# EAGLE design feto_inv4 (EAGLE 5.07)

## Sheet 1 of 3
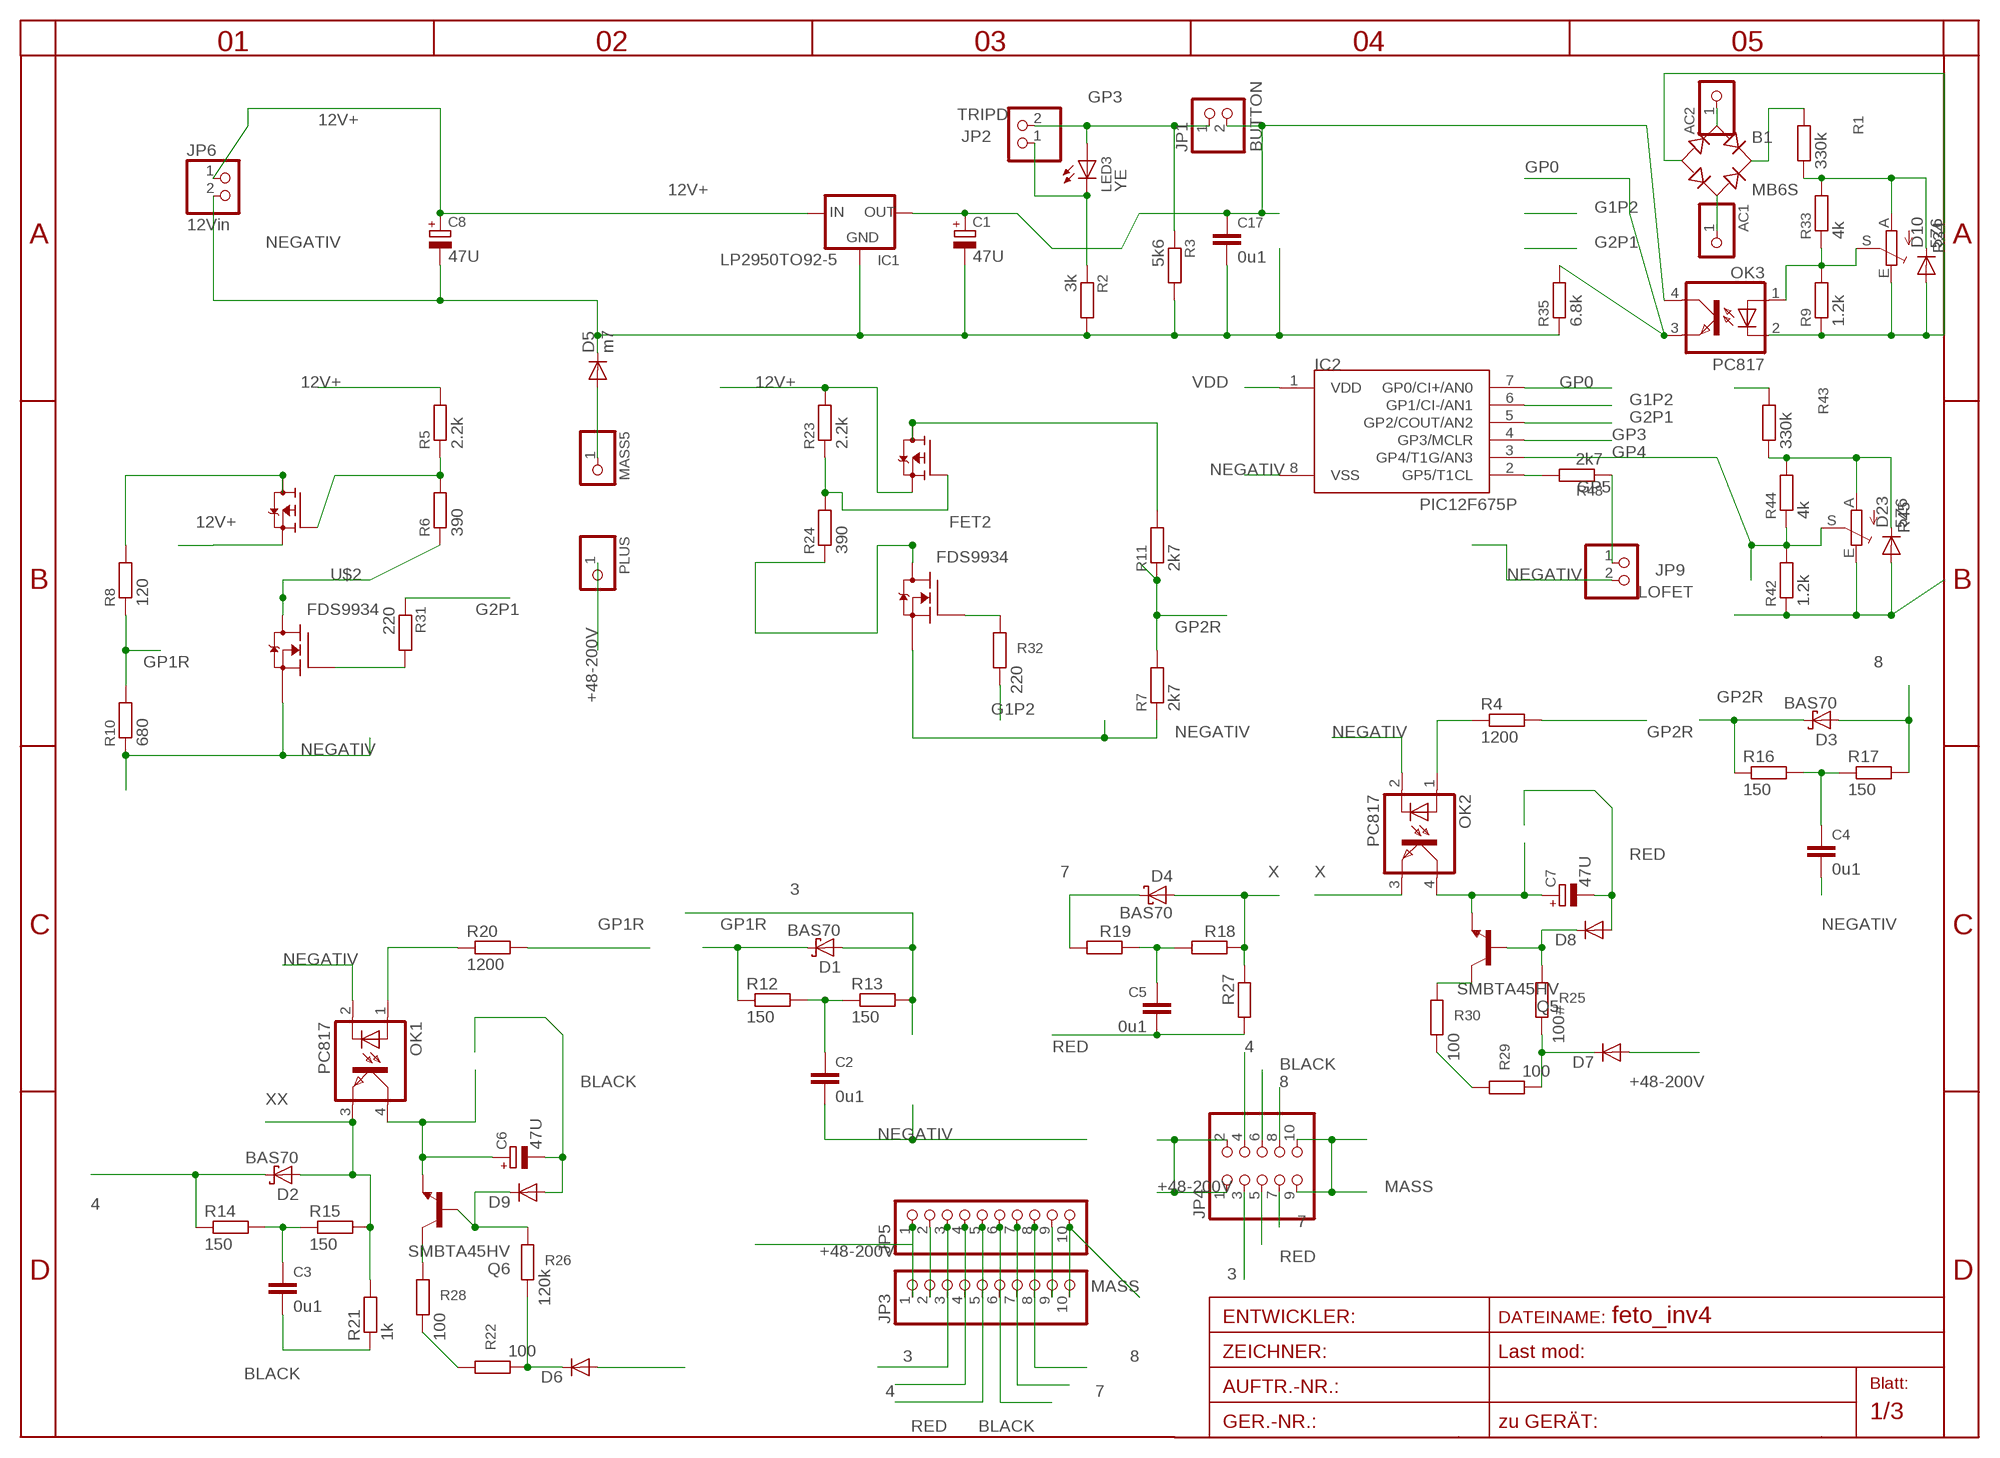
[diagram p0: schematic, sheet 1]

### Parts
AC1  PINHD-1X11MM6  [1X1MM8]
AC2  PINHD-1X11MM6  [1X1MM8]
B1  MB6S  [SOIC-4]
C1  47U  CPOL-EUE2.5-5  [E2,5-5]
C2  0u1  C-EUC1206  [C1206]
C3  0u1  C-EUC0805  [C0805]
C4  0u1  C-EUC1206  [C1206]
C5  0u1  C-EUC0805  [C0805]
C6  47U  CPOL-EUE2.5-6  [E2,5-6]
C7  47U  CPOL-EUE2.5-6  [E2,5-6]
C8  47U  CPOL-EUE2.5-7  [E2,5-7]
C17  0u1  C-EUC1206  [C1206]
D1  BAS70  [SOT23]
D2  BAS70  [SOT23]
D3  BAS70  [SOT23]
D4  BAS70  [SOT23]
D5  m7  DIODE-SMA-DO214  [SMA-DO214AC]
D6  DIODE-SMA-DO214  [SMA-DO214AC]
D7  DIODE-SMA-DO214  [SMA-DO214AC]
D8  DIODE-MINIMELF  [MINIMELF]
D9  DIODE-MINIMELF  [MINIMELF]
D10  5Z6  DIODE-MINIMELF  [MINIMELF]
D23  5Z6  DIODE-MINIMELF  [MINIMELF]
FET2  FDS9934  [SO-8]
IC1  LP2950TO92-5  [T092-5]
IC2  PIC12F675P  [DIL8]
JP1  BUTTON  PINHD-1X2STR  [1X02]
JP2  TRIPD  PINHD-1X2STR  [1X02]
JP3  PINHD-1X10  [1X10WIDE]
JP4  PINHD-2X5  [2X05]
JP5  PINHD-1X10  [1X10WIDE]
JP6  12Vin  PINHD-1X2STR  [1X02]
JP9  LOFET  PINHD-1X2STR  [1X02]
LED3  YE  LEDCHIPLED_1206  [CHIPLED_1206]
MASS5  PINHD-1X11MM6  [1X1MM8]
OK1  PC817  [DIL04]
OK2  PC817  [DIL04]
OK3  PC817  [DIL04]
PLUS  PINHD-1X11MM6  [1X1MM8]
Q5  SMBTA45HV  [SOT23HV]
Q6  SMBTA45HV  [SOT23HV]
R1  330k  R-EU_0204/5  [0204/5]
R2  3k  R-EU_R0805  [R0805]
R3  5k6  R-EU_R0805  [R0805]
R4  1200  R-EU_0204/7  [0204/7]
R5  2.2k  R-EU_R0805  [R0805]
R6  390  R-EU_R0805  [R0805]
R7  2k7  R-EU_R0805  [R0805]
R8  120  R-EU_R0805  [R0805]
R9  1.2k  R-EU_R0805  [R0805]
R10  680  R-EU_R0805  [R0805]
R11  2k7  R-EU_R0805  [R0805]
R12  150  R-EU_R0805  [R0805]
R13  150  R-EU_R0805  [R0805]
R14  150  R-EU_R0805  [R0805]
R15  150  R-EU_R0805  [R0805]
R16  150  R-EU_R0805  [R0805]
R17  150  R-EU_R0805  [R0805]
R18  R-EU_R0805  [R0805]
R19  R-EU_R0805  [R0805]
R20  1200  R-EU_0617/17  [0617/17]
R21  1k  R-EU_R0805  [R0805]
R22  100  R-EU_R1206  [R1206]
R23  2.2k  R-EU_R0805  [R0805]
R24  390  R-EU_R0805  [R0805]
R25  100#  R-EU_R1206  [R1206]
R26  120k  R-EU_R1206  [R1206]
R27  R-EU_R0805  [R0805]
R28  100  R-EU_R1206  [R1206]
R29  100  R-EU_R1206  [R1206]
R30  100  R-EU_R1206  [R1206]
R31  220  R-EU_R1206  [R1206]
R32  220  R-EU_R1206  [R1206]
R33  4k  R-EU_R0805  [R0805]
R34  TRIM_EU-S64W  [S64W]
R35  6.8k  R-EU_R0805  [R0805]
R42  1.2k  R-EU_R0805  [R0805]
R43  330k  R-EU_0207/50  [0207/50]
R44  4k  R-EU_R0805  [R0805]
R45  TRIM_EU-S64W  [S64W]
R48  2k7  R-EU_R0805  [R0805]
U$2  FDS9934  [SO-8]

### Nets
3: D1.1(A) JP3.3 JP4.3 JP5.3 R13.2 ; also sheet 3
4: D2.3(C) JP3.4 JP4.4 JP5.4 R14.1 ; also sheet 3
7: D4.3(C) JP3.7 JP4.7 JP5.7 R19.2 ; also sheet 3
8: D3.1(A) JP3.8 JP4.8 JP5.8 R17.2 ; also sheet 3
12V+: C8.+ FET2.3(Q2S) IC1.3(IN) JP6.1 R5.2 R23.2 U$2.3(Q2S)
+48-200V: D6.A D7.A JP3.1 JP4.1 JP4.2 JP5.1 PLUS.1 R43.2
BLACK: C3.2 C6.- D9.A JP3.6 JP4.6 JP5.6 R21.1 ; also sheet 3
G1P2: IC2.6(GP1/CI-/AN1) R32.1
G2P1: IC2.5(GP2/COUT/AN2) R31.1
GP0: IC2.7(GP0/CI+/AN0) OK3.3(EMIT) R35.2
GP1R: D1.3(C) R8.1 R10.2 R12.1 R20.2
GP2R: D3.3(C) R4.2 R7.2 R11.1 R16.1
GP3: IC2.4(GP3/MCLR) JP1.1 JP2.2 LED3.A R3.1 ; also sheet 3
GP4: IC2.3(GP4/T1G/AN3) R42.2 R44.1 R45.S
GP5: JP9.1 R48.1
MASS: D5.A JP3.10 JP4.9 JP4.10 JP5.10 MASS5.1 ; also sheet 3
N$2: FET2.2(Q1G) R32.2
N$3: C3.1 R14.2 R15.1
N$4: R5.1 R6.2 U$2.4(Q2G)
N$5: FET2.5(Q2D2) FET2.6(Q2D) R11.2
N$6: R31.2 U$2.2(Q1G)
N$7: C6.+ OK1.4(COL) Q6.2(E)
N$8: C5.1 R18.2 R19.1
N$9: FET2.7(Q1D2) FET2.8(Q1D1) R24.1
N$11: R6.1 U$2.7(Q1D2) U$2.8(Q1D1)
N$12: C2.1 R12.2 R13.1
N$13: OK2.1(A) R4.1
N$14: C7.+ OK2.4(COL) Q5.2(E)
N$15: JP2.1 LED3.C R2.1
N$16: C4.1 R16.2 R17.1
N$17: OK1.1(A) R20.1
N$20: D7.K(C) R25.1 R29.1
N$21: R8.2 U$2.5(Q2D2) U$2.6(Q2D)
N$22: FET2.4(Q2G) R23.1 R24.2
N$23: D6.K(C) R22.1 R26.1
N$24: Q6.3(C) R28.2
N$25: JP3.2 JP5.2
N$26: R22.2 R28.1
N$27: D9.C Q6.1(B) R26.2
N$28: R29.2 R30.1
N$31: D8.C Q5.1(B) R25.2
N$33: Q5.3(C) R30.2
N$34: JP3.9 JP5.9
N$35: OK3.1(A) R9.2 R33.1 R34.S
N$36: D10.C R1.1 R33.2 R34.A
N$37: B1.- D10.A OK3.2(C) R9.1 R34.E
N$38: AC1.1 B1.~2(AC2)
N$39: AC2.1 B1.~1(AC1)
N$40: B1.+ R1.2
N$41: D23.C R43.1 R44.2 R45.A
N$46: IC2.2(GP5/T1CL) R48.2
NEGATIV: C1.- C2.2 C4.2 C8.- C17.2 D5.K(C) D23.A FET2.1(Q1S) IC1.2(GND) IC2.8(VSS) JP6.2 JP9.2 OK1.2(C) OK2.2(C) R2.2 R3.2 R7.1 R10.1 R35.1 R42.1 R45.E U$2.1(Q1S)
RED: C5.2 C7.- D8.A JP3.5 JP4.5 JP5.5 R27.2 ; also sheet 3
VDD: C1.+ C17.1 IC1.1(OUT) IC2.1(VDD) JP1.2 OK3.4(COL) ; also sheet 3
X: D4.1(A) OK2.3(EMIT) R18.1 R27.1
XX: D2.1(A) OK1.3(EMIT) R15.2 R21.2

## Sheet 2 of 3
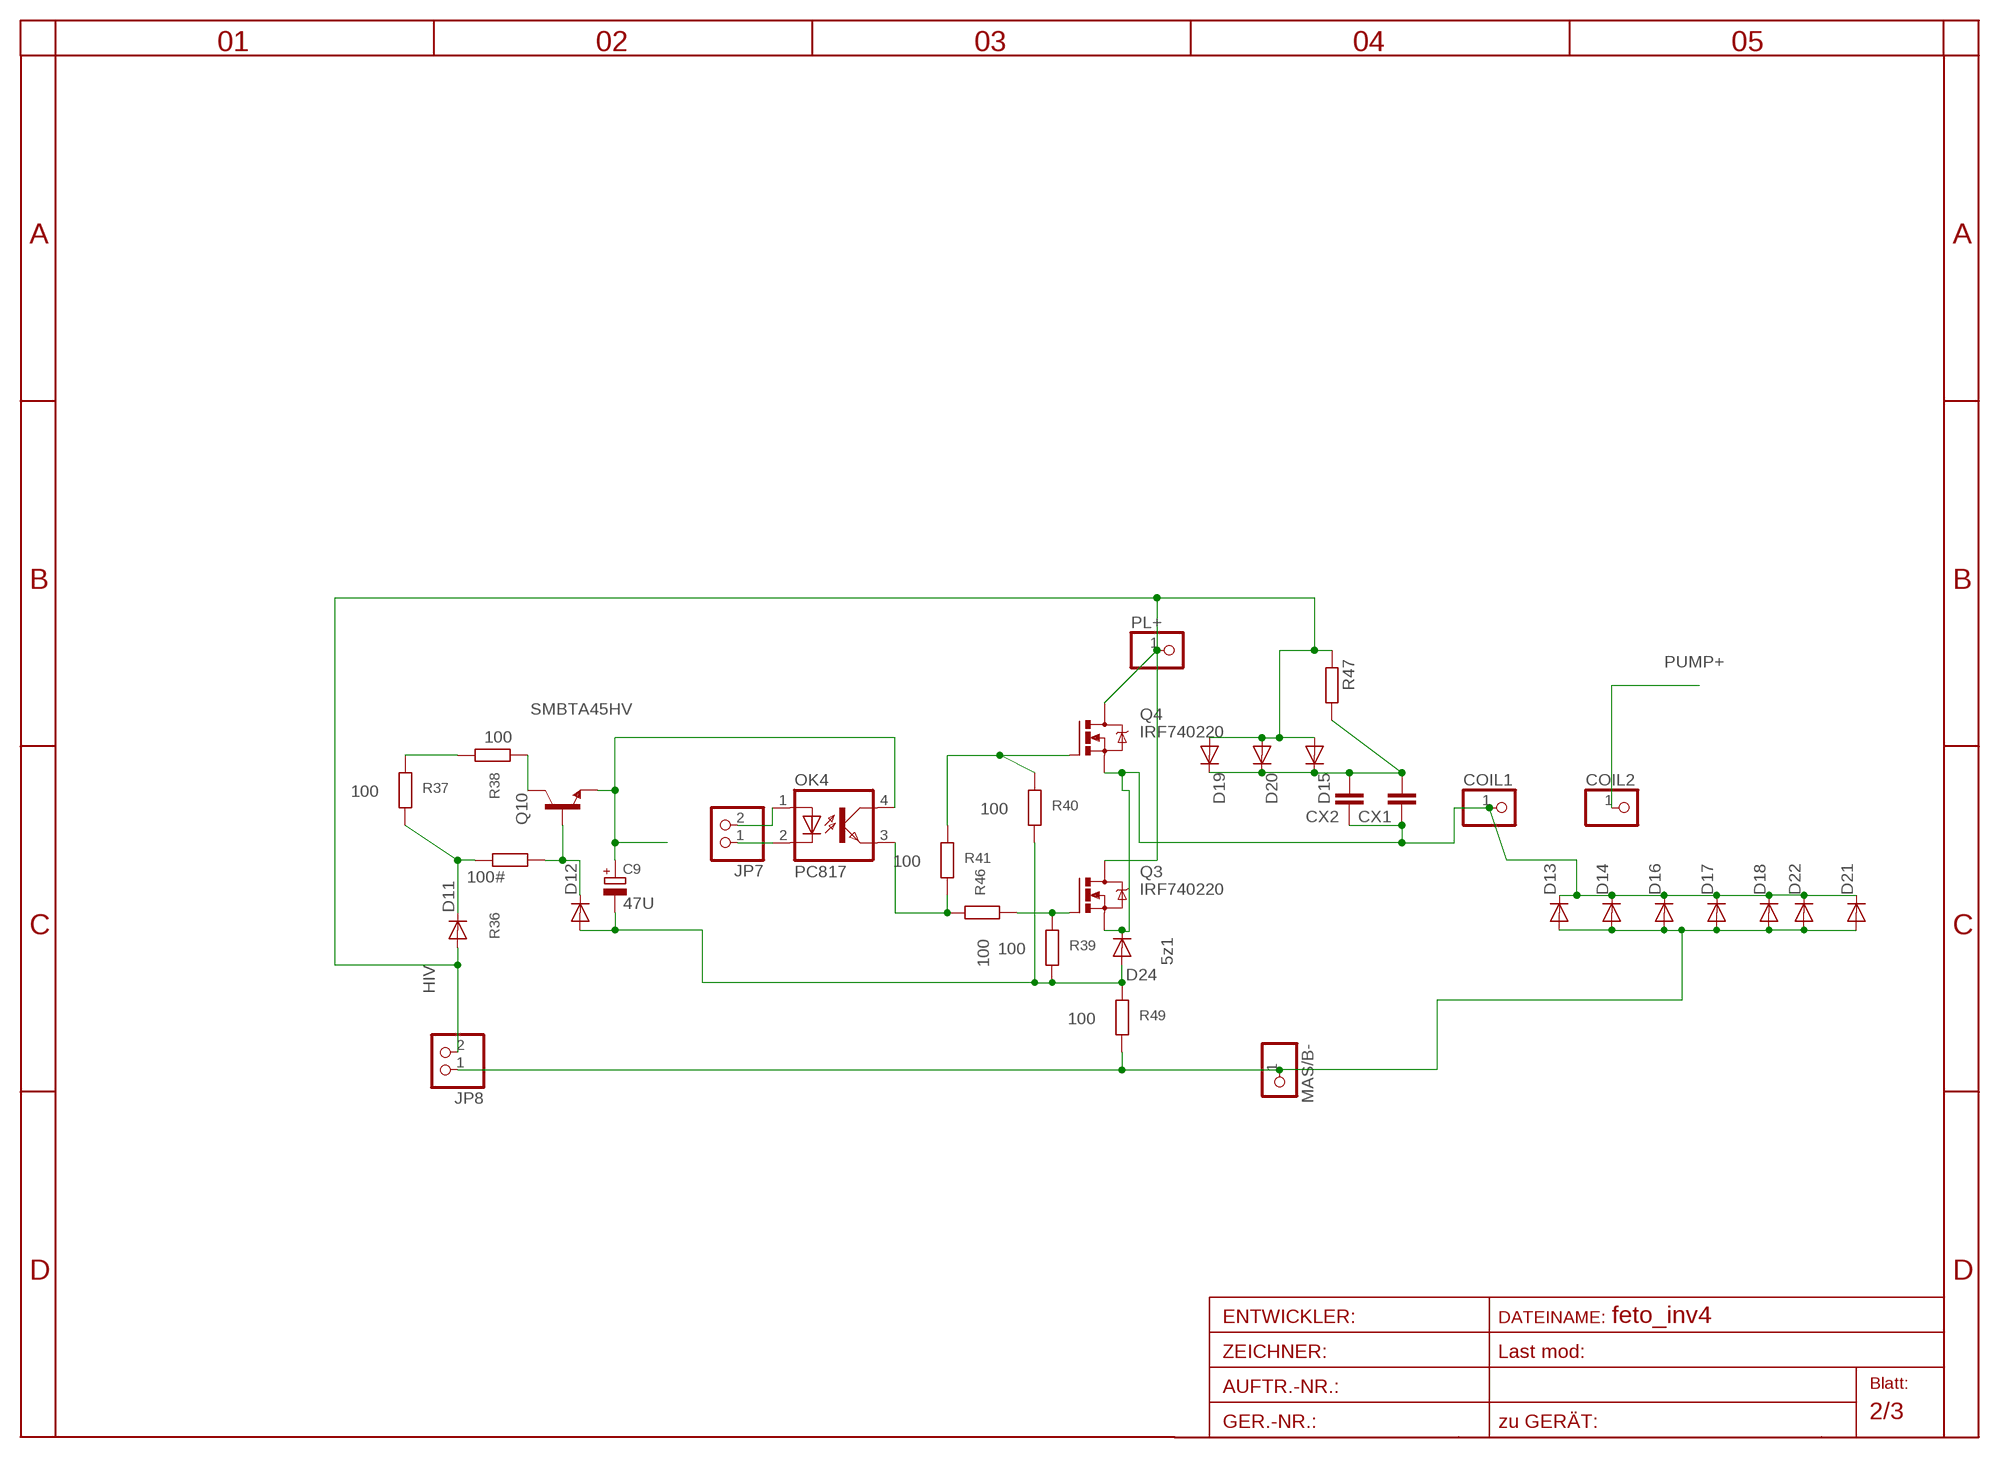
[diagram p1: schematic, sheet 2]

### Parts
C9  47U  CPOL-EUE2.5-6  [E2,5-6]
COIL1  PINHD-1X14.5MM  [1X4MM5]
COIL2  PINHD-1X14.5MM  [1X4MM5]
CX1  CXXC15B6  [XC15B6]
CX2  CXXC15B6  [XC15B6]
D11  DIODE-SMA-DO214  [SMA-DO214AC]
D12  DIODE-MINIMELF  [MINIMELF]
D13  DIODE-SMC  [SMC]
D14  DIODE-SMC  [SMC]
D15  DIODE-SMC  [SMC]
D16  DIODE-SMC  [SMC]
D17  DIODE-SMC  [SMC]
D18  DIODE-SMC  [SMC]
D19  DIODE-SMC  [SMC]
D20  DIODE-SMC  [SMC]
D21  DIODE-SMC  [SMC]
D22  DIODE-SMC  [SMC]
D24  5z1  DIODE-MINIMELF  [MINIMELF]
JP7  PINHD-1X2STR  [1X02]
JP8  PINHD-1X2STR  [1X02]
MAS/B-  PINHD-1X14.5MM  [1X4MM5]
OK4  PC817  [DIL04]
PL+  PINHD-1X14.5MM  [1X4MM5]
Q3  IRF740220  [TO220BV]
Q4  IRF740220  [TO220BV]
Q10  SMBTA45HV  [SOT23HV]
R36  100#  R-EU_R1206  [R1206]
R37  100  R-EU_R1206  [R1206]
R38  100  R-EU_R1206  [R1206]
R39  100  R-EU_0207/30  [0207/30]
R40  100  R-EU_0207/15  [0207/15]
R41  100  R-EU_0207/12  [0207/12]
R46  100  R-EU_0207/25  [0207/25]
R47  R-EU_CERAM35  [CERAM35]
R49  100  R-EU_R1206  [R1206]

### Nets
BATT-: C9.- D12.A D24.A R39.1 R40.1 R49.2
COIL1: COIL1.1 CX1.1 CX2.1 D13.C D14.C D16.C D17.C D18.C D21.C D22.C D24.C Q3.S Q4.S
HIV: D11.A D15.A D19.A D20.A JP8.2 PL+.1 Q3.D Q4.D R47.1
MINUS: D13.A D14.A D16.A D17.A D18.A D21.A D22.A JP8.1 MAS/B-.1 R49.1 ; also sheet 3
N$1: Q4.G R40.2 R41.2
N$42: JP7.1 OK4.2(C)
N$43: OK4.3(EMIT) R41.1 R46.2
N$44: JP7.2 OK4.1(A)
N$45: Q3.G R39.2 R46.1
N$48: C9.+ OK4.4(COL) Q10.2(E)
N$49: D11.K(C) R36.1 R37.1
N$50: R37.2 R38.1
N$51: D12.C Q10.1(B) R36.2
PUMP+: COIL2.1 ; also sheet 3
Q1: Q10.3(C) R38.2
SNUB: CX1.2 CX2.2 D15.C D19.C D20.C R47.2

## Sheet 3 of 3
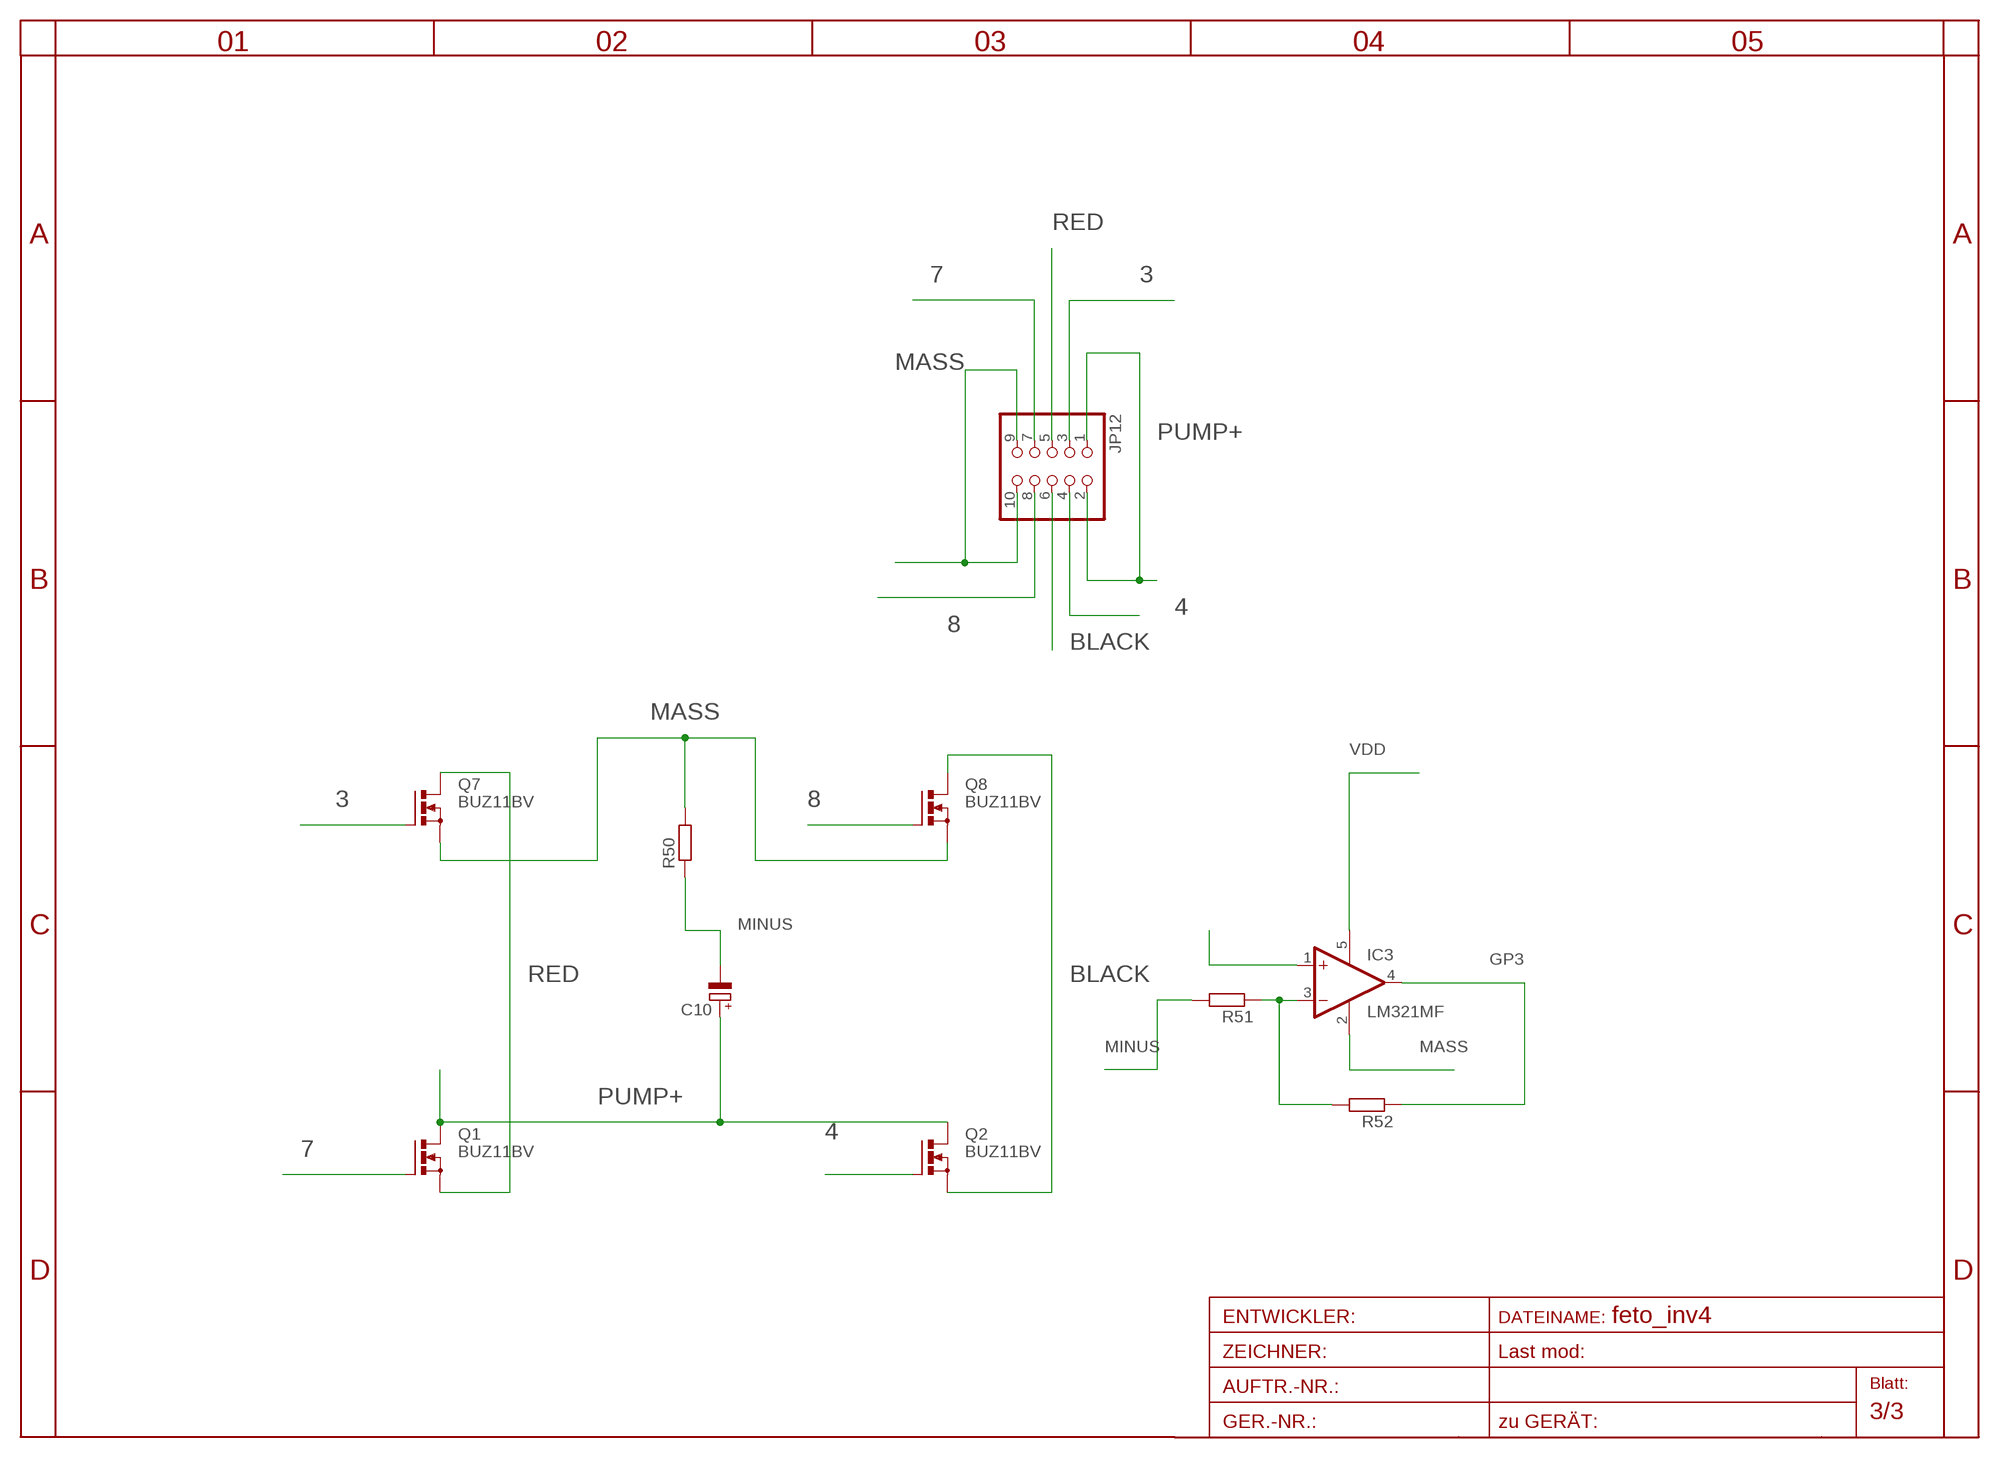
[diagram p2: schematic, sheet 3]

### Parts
C10  CPOL-EUE5-13  [E5-13]
IC3  LM321MF  [SOT23-5]
JP12  PINHD-2X5  [2X05]
Q1  BUZ11BV  [TO220BV]
Q2  BUZ11BV  [TO220BV]
Q7  BUZ11BV  [TO220BV]
Q8  BUZ11BV  [TO220BV]
R50  R-EU_0207/10  [0207/10]
R51  R-EU_0207/10  [0207/10]
R52  R-EU_0207/10  [0207/10]

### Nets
3: JP12.3 Q7.G ; also sheet 1
4: JP12.4 Q2.G ; also sheet 1
7: JP12.7 Q1.G ; also sheet 1
8: JP12.8 Q8.G ; also sheet 1
BLACK: JP12.6 Q2.S Q8.D ; also sheet 1
GP3: IC3.4(OUT) R52.1 ; also sheet 1
MASS: IC3.1(+IN) IC3.2(V-) JP12.9 JP12.10 Q7.S Q8.S R50.2 ; also sheet 1
MINUS: C10.- R50.1 R51.2 ; also sheet 2
N$52: IC3.3(-IN) R51.1 R52.2
PUMP+: C10.+ JP12.1 JP12.2 Q1.D Q2.D ; also sheet 2
RED: JP12.5 Q1.S Q7.D ; also sheet 1
VDD: IC3.5(V+) ; also sheet 1

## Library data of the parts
AC1 AC2 COIL1 COIL2 MAS/B- MASS5 PL+ PLUS = pinhead:PINHD-1X1: PIN HEADER
B1 = rectifier:MB*S: Bridge Rectifier Source: http://www.fairchildsemi.com/ds/MB/MB6S.pdf
C1 C6-C9 = rcl-2:CPOL-EU: POLARIZED CAPACITOR, European symbol
C2-C5 C17 = rcl-2:C-EU: CAPACITOR, European symbol
C10 = rcl:CPOL-EU: POLARIZED CAPACITOR, European symbol
CX1 CX2 = rcl:CX: X CAPACITOR
D1-D4 = diode:BAS70: Silicon Schottky Diodes
D5-D24 = diode:DIODE-: DIODE
FET2 U$2 = transistor-fet:FDS9934
IC1 = v-reg:LP2950?*: Source: http://cache.national.com/ds/LP/LP2950.pdf
IC2 = microchip-3:PIC12F6*: uPC nW 1k Program Flash memory 2x Timer Comparator 10b A/D converter/ 4xIN
IC3 = linear:LM321?*: Low Power Single Op Amp Source: http://cache.national.com/ds/LM/LM321.pdf
JP1 JP2 JP6-JP9 = pinhead:PINHD-1X2: PIN HEADER
JP3 JP5 = pinhead:PINHD-1X10: PIN HEADER
JP4 JP12 = pinhead:PINHD-2X5: PIN HEADER
LED3 = led:LED: LED
OK1-OK4 = optocoupler:PC817: SHARP OPTO COUPLER
Q1 Q2 Q7 Q8 = transistor-power:BUZ11: N-CHANNEL MOS FET
Q3 Q4 = transistor-power:IRF740: N-CHANNEL MOS FET
Q5 Q6 Q10 = transistor-npn:SMBTA45
R1-R3 R5-R11 R22-R26 R28-R33 R35-R44 R46 R48 R49 = rcl-2:R-EU_: RESISTOR, European symbol
R4 R12-R21 R27 R47 R50-R52 = rcl:R-EU_: RESISTOR, European symbol
R34 R45 = pot:TRIM_EU-: POTENTIOMETER

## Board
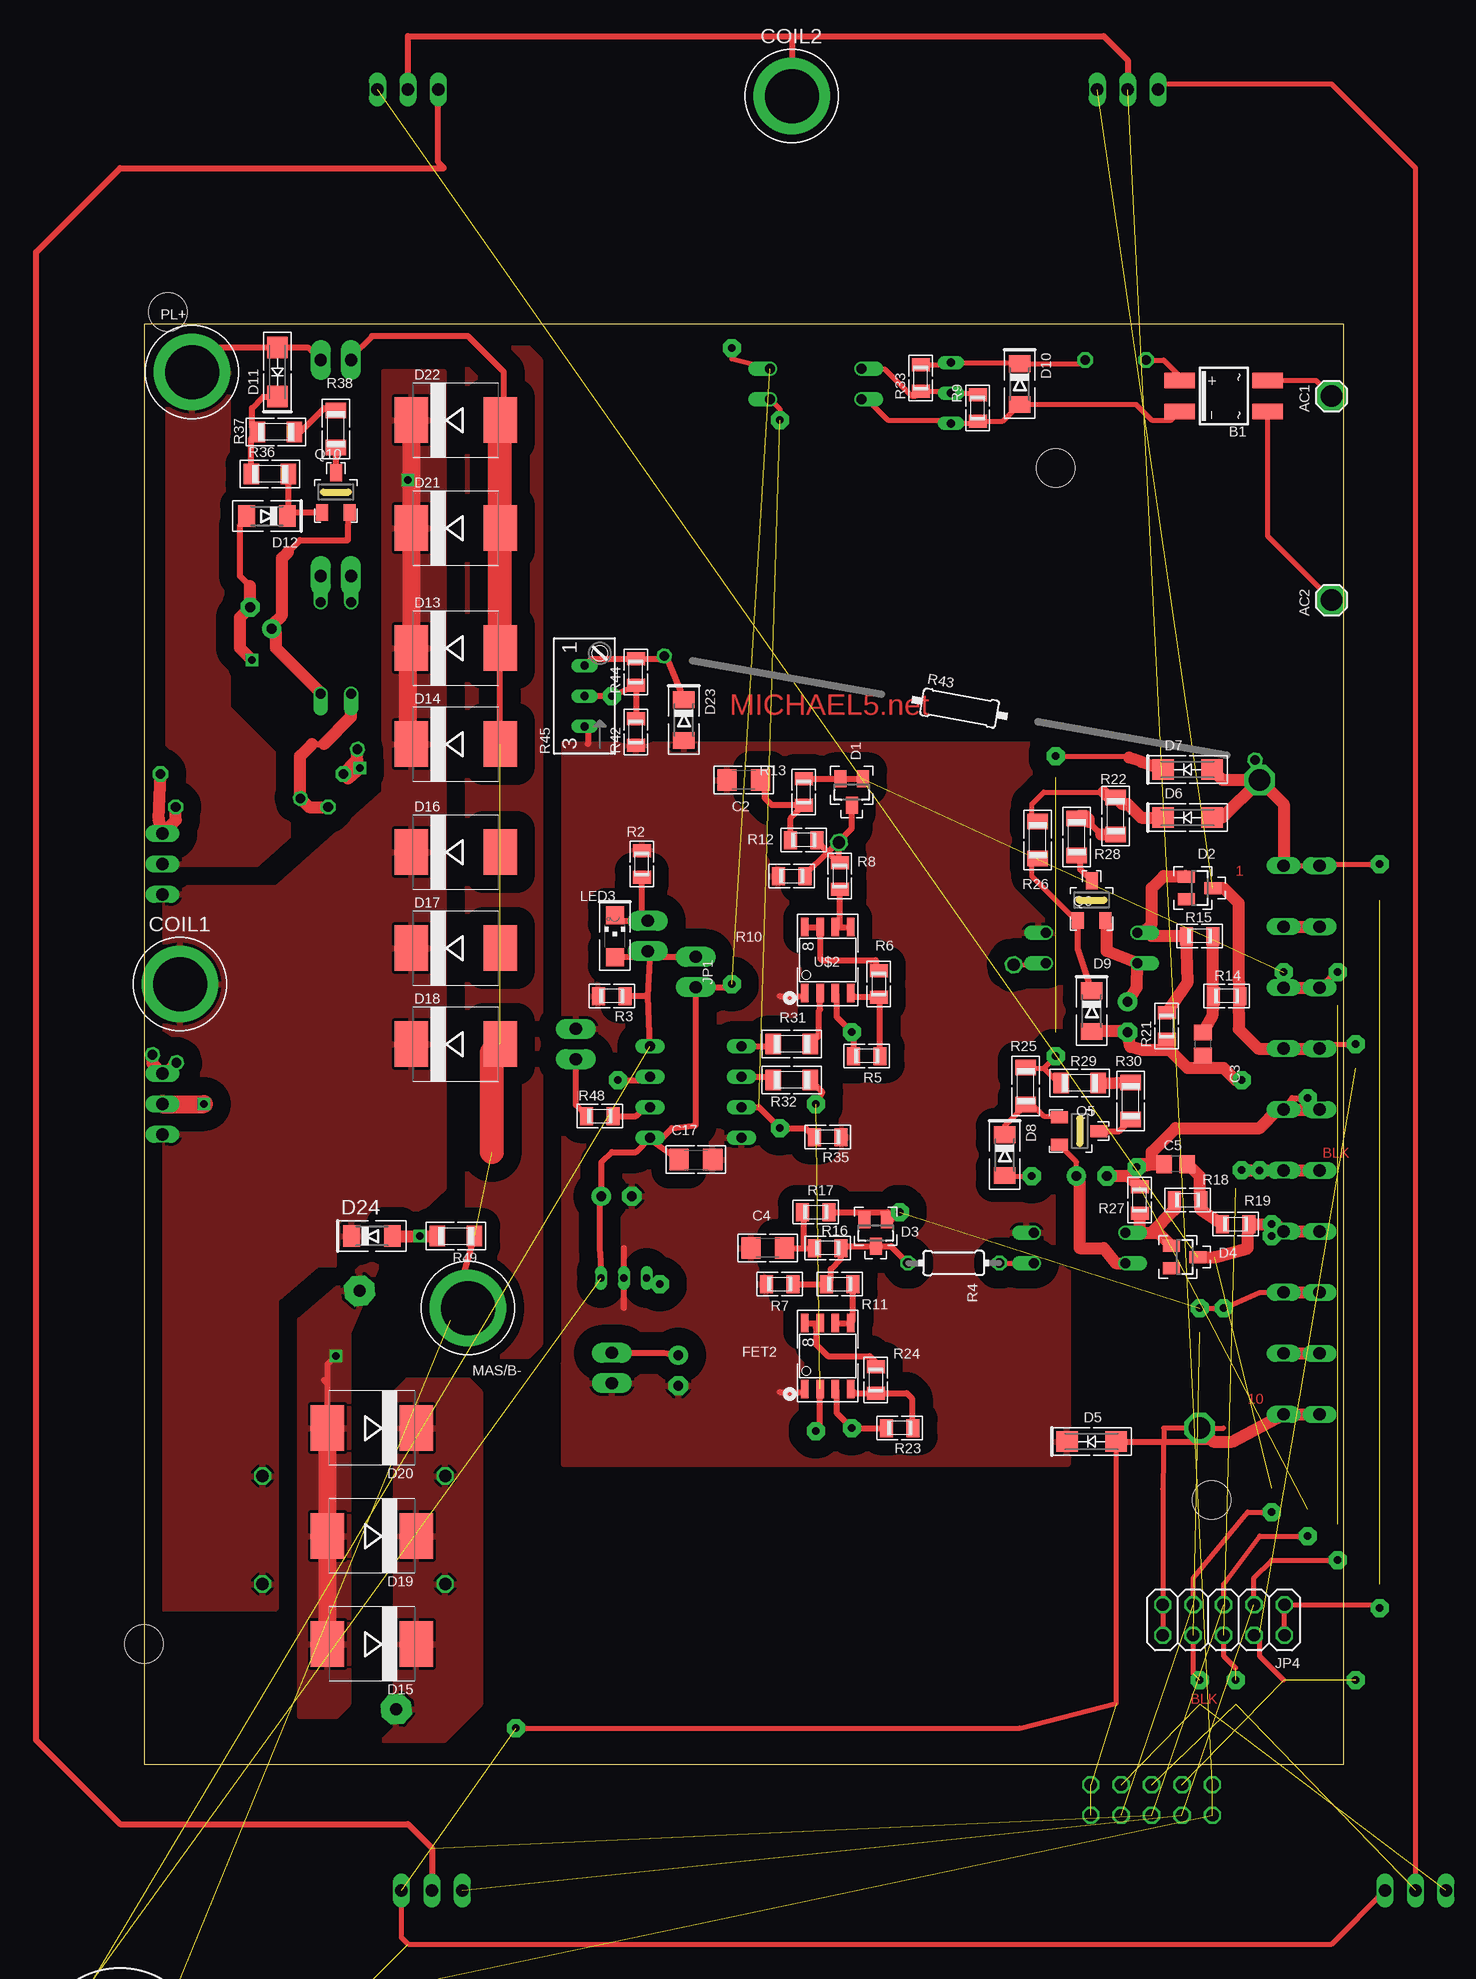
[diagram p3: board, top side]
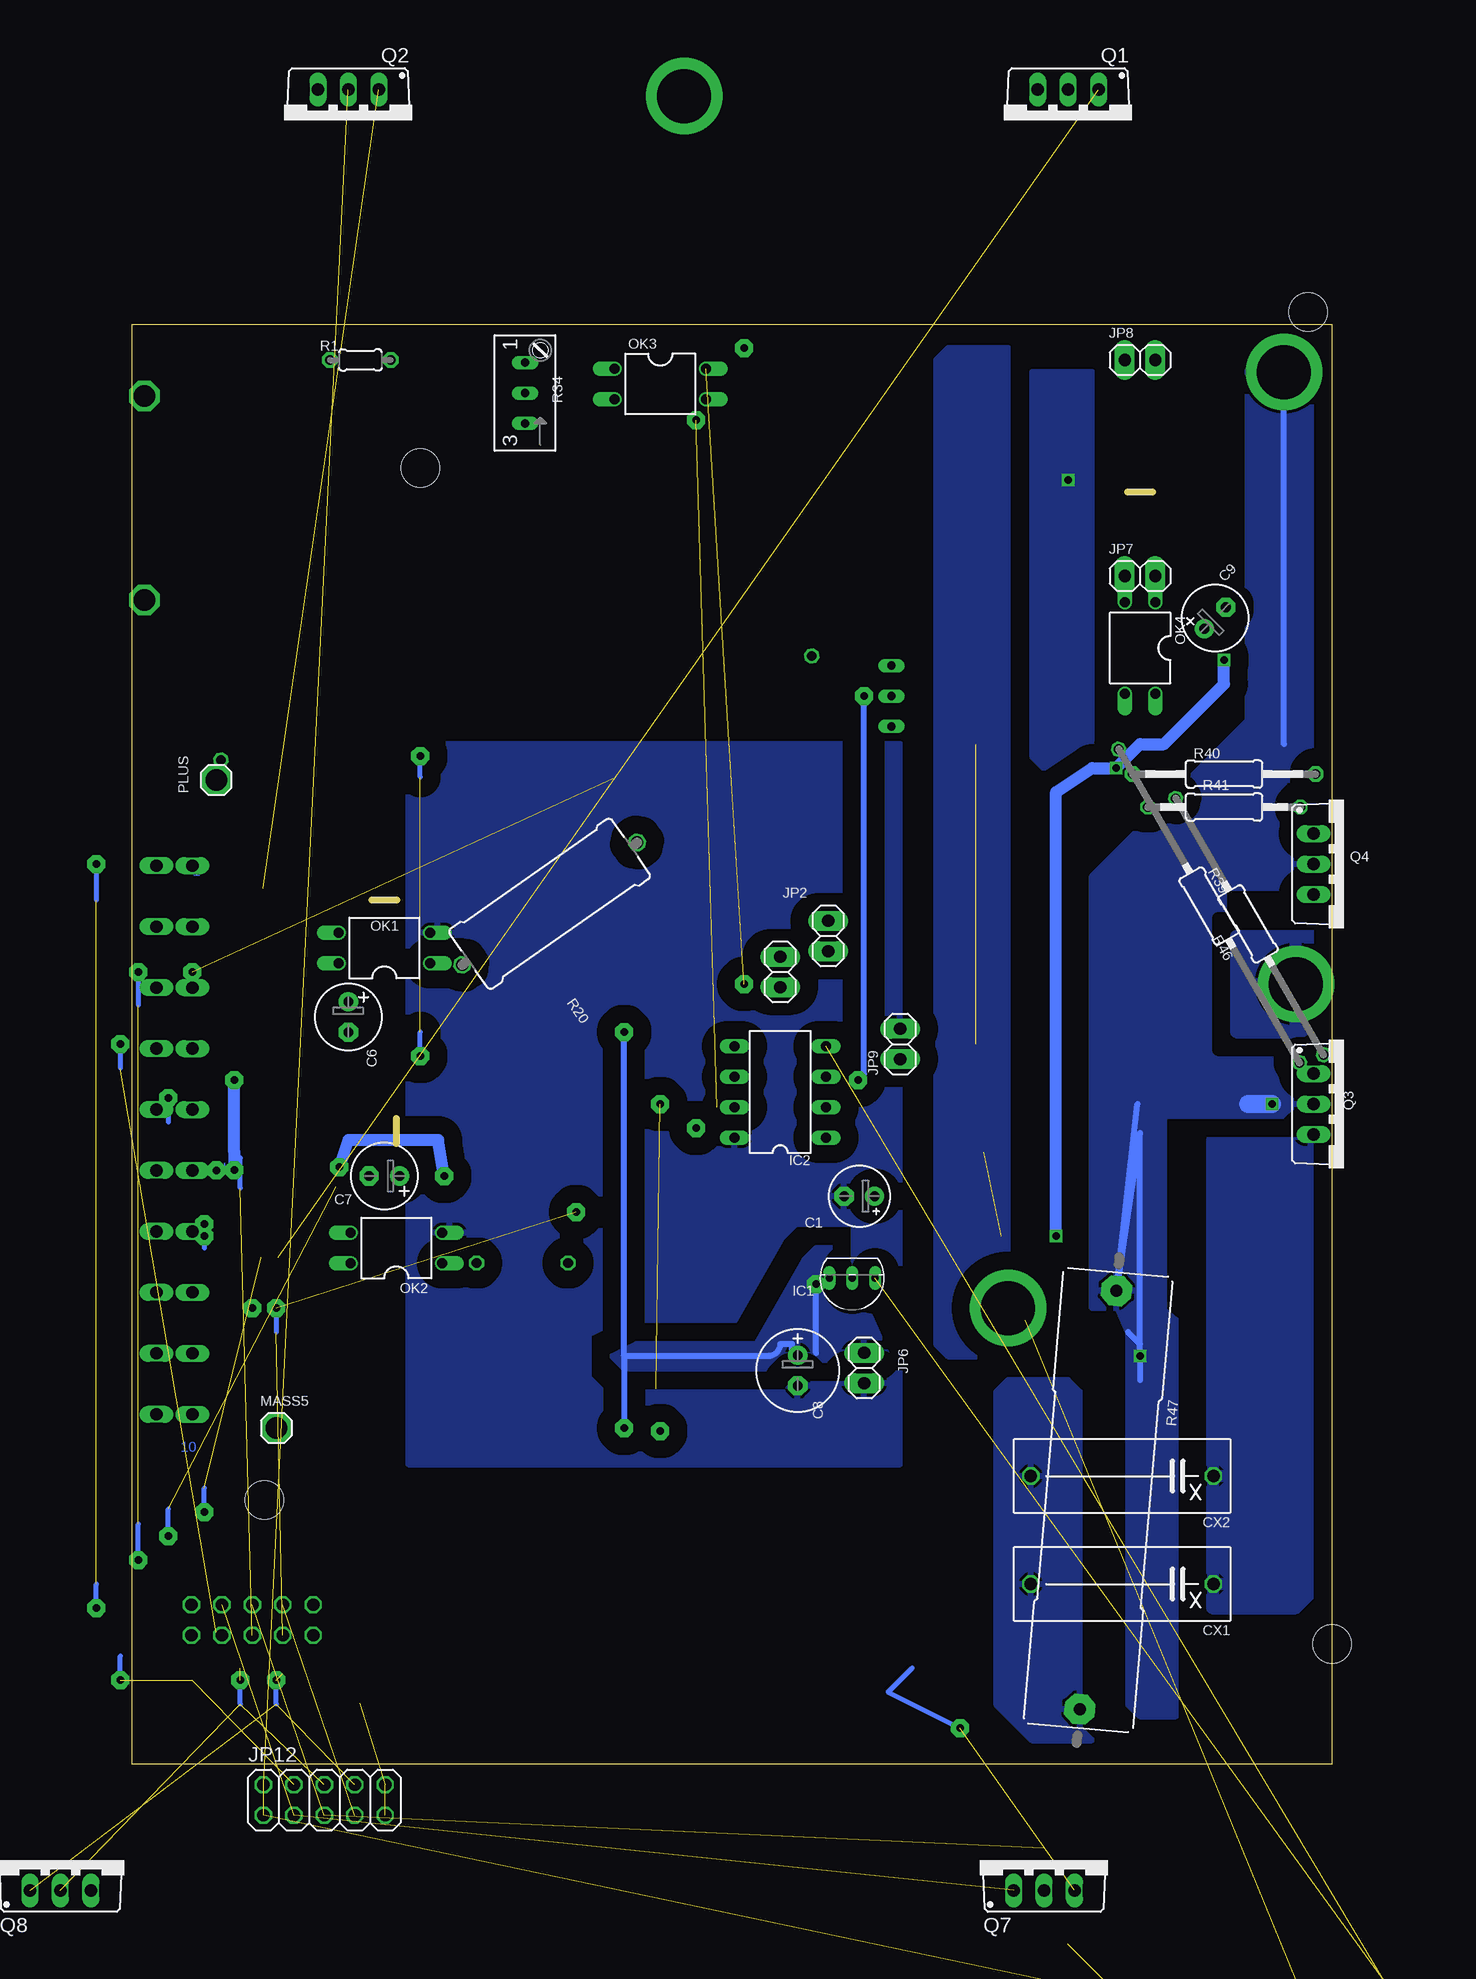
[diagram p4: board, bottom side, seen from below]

Size 100 x 120 mm. Coordinates in mm from the lower left corner, seen from the top.
Outline: 0,0 100,0 100,120 0,120 0,0
Copper layers (1*16): Top 0.035mm / dielectric 1.5mm / Bottom 0.035mm
Design rules "default *": minimum track width 12mil, minimum drill 24mil, track to track 8mil, track to pad 8mil, pad to pad 8mil, via to via 8mil, smd to smd 8mil, copper to edge 40mil, drill to drill 8mil, minimum pad ring 8mil, minimum via ring 8mil, stop-mask expansion 4mil, vias tented up to drill 0mil, thermal gap 10mil
Holes 3.2 mm at 2,121 0,10 76,108 89,22

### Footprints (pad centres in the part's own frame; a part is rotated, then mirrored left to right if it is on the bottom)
1X1MM8 = drill 1.8 pad 2.54 octagon: 1 0,0
SOIC-4 = smd 1.27 x 2.54: + 1.3,3.685; - -1.3,3.685; ~1 -1.3,-3.685; ~2 1.3,-3.685
E2,5-5 = drill 0.813 pad 1.6 round: + -1.27,0 | drill 0.813 pad 1.6 octagon: - 1.27,0
C1206 = smd 1.6 x 1.8: 1 -1.4,0; 2 1.4,0
C0805 = smd 1.3 x 1.5: 1 -0.95,0; 2 0.95,0
E2,5-6 = drill 0.813 pad 1.6 round: + -1.27,0 | drill 0.813 pad 1.6 octagon: - 1.27,0
E2,5-7 = drill 0.813 pad 1.6 round: + -1.27,0 | drill 0.813 pad 1.6 octagon: - 1.27,0
E5-13 = drill 1.016 pad 2.54 round: + -2.54,0 | drill 1.016 pad 2.54 octagon: - 2.54,0
1X4MM5 = drill 4.5 pad 6.35 round: 1 0,0
XC15B6 = drill 1.016 octagon: 1 -7.62,0; 2 7.62,0
SOT23 = smd 1 x 1.4: 1 -0.95,-1.1; 2 0.95,-1.1; 3 0,1.1
SMA-DO214AC = smd 1.8 x 1.7: A 2.05,-0.127; K -2.05,-0.127
MINIMELF = smd 1.4 x 1.8: A 1.7,0; C -1.7,0
SMC = smd 2.8 x 3.8: A 3.7,0; C -3.7,0
SO-8 = smd 1.524 x 0.61: 1 -2.743,1.905; 2 -2.743,0.635; 3 -2.743,-0.635; 4 -2.743,-1.905; 5 2.743,-1.905; 6 2.743,-0.635; 7 2.743,0.635; 8 2.743,1.905
T092-5 = drill 0.6 pad 0.813 long: 1 -1.905,0; 2 0,0; 3 1.905,0
DIL8 = drill 0.813 long: 1 -3.81,-3.81; 2 -1.27,-3.81; 3 1.27,-3.81; 4 3.81,-3.81; 5 3.81,3.81; 6 1.27,3.81; 7 -1.27,3.81; 8 -3.81,3.81
SOT23-5 = smd 0.6 x 1.2: 1 -0.95,-1.306; 2 0,-1.306; 3 0.95,-1.306; 4 0.95,1.306; 5 -0.95,1.306
1X02 = drill 1.016 pad 1.676 long: 1 -1.27,0; 2 1.27,0
1X10WIDE = drill 1.016 long: 1 -22.86,0; 2 -17.78,0; 3 -12.7,0; 4 -7.62,0; 5 -2.54,0; 6 2.54,0; 7 7.62,0; 8 12.7,0; 9 17.78,0; 10 22.86,0
2X05 = drill 1.016 octagon: 1 -5.08,-1.27; 2 -5.08,1.27; 3 -2.54,-1.27; 4 -2.54,1.27; 5 0,-1.27; 6 0,1.27; 7 2.54,-1.27; 8 2.54,1.27; 9 5.08,-1.27; 10 5.08,1.27
CHIPLED_1206 = smd 1.5 x 1.5: A 0,-1.75; C 0,1.75
DIL04 = drill 0.813 offset: 1 -1.27,-3.81; 2 1.27,-3.81; 3 1.27,3.81; 4 -1.27,3.81
TO220BV = drill 1.016 long: D 0,-2.54; G -2.54,-2.54; S 2.54,-2.54
SOT23HV = smd 1 x 1.4: 1 -1.15,-1.7; 2 1.15,-1.7; 3 0,1.6
0204/5 = drill 0.8 pad 1.27 octagon: 1 -2.54,0; 2 2.54,0
R0805 = smd 1.1 x 1.5: 1 -1.1,0; 2 1.1,0
0204/7 = drill 0.813 octagon: 1 -3.81,0; 2 3.81,0
0617/17 = drill 1.016 octagon: 1 -8.89,0; 2 8.89,0
R1206 = smd 1.3 x 1.7: 1 -1.55,0; 2 1.55,0
S64W = drill 0.7 long: A 2.54,1.27; E -2.54,1.27; S 0,1.27
0207/30 = drill 0.813 octagon: 1 -15.08,0; 2 15.08,0
0207/15 = drill 0.8 pad 1.27 octagon: 1 -7.62,0; 2 7.62,0
0207/12 = drill 0.813 octagon: 1 -6.35,0; 2 6.35,0
0207/50 = drill 0.813 octagon: 1 -25,0; 2 25,0
0207/25 = drill 0.813 octagon: 1 -12.58,0; 2 12.08,0
CERAM35 = drill 1 pad 2.54 octagon: 1 -17.5,0; 2 17.5,0
0207/10 = drill 0.813 octagon: 1 -5.08,0; 2 5.08,0

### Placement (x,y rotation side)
AC1  99,114 90 top
AC2  99,97 90 top
B1  90,114 90 top
C1  39.4,47.32 180 bottom
C2  50,82 180 top
C3  88.25,60 270 top
C4  52,43 180 top
C5  86,50 180 top
C6  82,62.25 270 bottom
C7  79,49 180 bottom
C8  44.55,32.8 270 bottom
C9  9.75,95.5 45 bottom
C10  not placed on the board
C17  46.01,50.37 0 top
COIL1  3,65 0 top
COIL2  54,139 0 top  (outside the outline)
CX1  17.5,15 180 bottom
CX2  17.5,24 180 bottom
D1  59,81 180 top
D2  88,73 270 top
D3  61,44.25 180 top
D4  86.75,42.25 270 top
D5  79,27 0 top
D6  87,79 0 top
D7  87,83 0 top
D8  71.75,50.75 270 top
D9  79,62.75 270 top
D10  73,115 270 top
D11  11,116 90 top
D12  10.25,104 180 top
D13  26,93 0 top
D14  26,85 0 top
D15  19,10 180 top
D16  26,76 0 top
D17  26,68 0 top
D18  26,60 0 top
D19  19,19 180 top
D20  19,28 180 top
D21  26,103 0 top
D22  26,112 0 top
D23  45,87 270 top
D24  19,44 0 top
FET2  57,34 90 top
IC1  40,40.5 180 bottom
IC2  46,56 90 bottom
IC3  not placed on the board
JP1  46,66 270 bottom
JP2  42,69 270 bottom
JP3  95,52 270 bottom
JP4  90,12 180 top
JP5  98,52 270 top
JP6  39,33 270 bottom
JP7  16,99 0 bottom
JP8  16,117 0 bottom
JP9  36,60 90 bottom
JP12  84,-3 0 bottom
LED3  39.25,69 0 top
MAS/B-  27,38 0 top
MASS5  88,28 0 bottom
OK1  79,68 90 bottom
OK2  78,43 90 bottom
OK3  56,115 270 bottom
OK4  16,93 180 bottom
PL+  4,116 0 top
PLUS  93,82 180 bottom
Q1  22,137 180 bottom  (outside the outline)
Q2  82,137 180 bottom  (outside the outline)
Q3  -1,55 270 bottom
Q4  -1,75 270 bottom
Q5  78,52.75 270 top
Q6  79,72 0 top
Q7  24,-8 0 bottom  (outside the outline)
Q8  106,-8 0 bottom  (outside the outline)
Q10  16,106 0 top
R1  81,117 180 bottom
R2  41.5,75 90 top
R3  39,64 180 top
R4  67.5,41.75 180 top
R5  60.25,59 180 top
R6  61.25,65 270 top
R7  53,40 0 top
R8  58,74 270 top
R9  69.5,113 90 top
R10  54,74 0 top
R11  58,40 0 top
R12  55,77 180 top
R13  55,81 90 top
R14  90.25,64 180 top
R15  88,69 180 top
R16  57,43 180 top
R17  56,46 0 top
R18  87,47 0 top
R19  91,45 0 top
R20  65.22,71.69 35 bottom
R21  85.25,61.5 90 top
R22  81,79 270 top
R23  63,28 180 top
R24  61,32 270 top
R25  73.5,56.5 270 top
R26  74.5,77 270 top
R27  83,47 90 top
R28  77.75,77.25 270 top
R29  78,56.75 0 top
R30  82.25,55.25 270 top
R31  54,60 0 top
R32  54,57 0 top
R33  64.75,115.5 90 top
R34  66,114.25 90 bottom
R35  57,52.25 180 top
R36  10.5,107.5 0 top
R37  11,111 0 top
R38  16,111.25 270 top
R39  10.25,71.5 300 bottom
R40  9,82.5 0 bottom
R41  9,79.75 0 bottom
R42  41,86 90 top
R43  68,88 350 top
R44  41,91 90 top
R45  38,89 90 top
R46  7,70 120 bottom
R47  19.5,22 265 bottom
R48  38,54 0 top
R49  26,44 180 top
R50  not placed on the board
R51  not placed on the board
R52  not placed on the board
U$2  57,67 90 top

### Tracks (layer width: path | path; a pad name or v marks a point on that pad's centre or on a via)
3  (via drill 0.6 pad 1.5)  (4 unrouted)
  Top 0.406: JP4.3 92.54,15.54 94,17 v99.5,17 | 99,65 98.3,65 JP5.3 99,65.7 v99.5,66
  Top 0.5: R13.2 D1.1
  Top 1: v95,66 JP3.3 JP5.3
  Bottom 0.406: v99.5,17 99.5,20 | v99.5,66 99.5,63.25
4  (via drill 0.6 pad 1.5)  (4 unrouted)
  Top 0.406: JP4.4 92.73,10.73 93,11 93,9 95,7 | JP5.4 98.38,60 v101,60
  Top 1: D2.3 90,73 91.25,71.75 91.25,65.5 91.35,64.4 R14.1 91.25,62.65 91.25,61.25 92.88,59.62 JP3.4 JP5.4
  Bottom 0.406: v101,7 101,9 | v101,60 101,58
7  (via drill 0.6 pad 1.5)  (3 unrouted)
  Top 0.406: JP4.7 87.46,15.46 92,21 v94,21 | JP5.7 98.38,44 | v94,45 v94,44
  Top 1: D4.3 89.25,42.25 92,43 92,43.9 R19.2 | JP3.7 JP5.7
  Top 1.016: R19.2 v94,45 94.38,45 JP3.7
  Bottom 0.406: v94,44 94,43 | v94,21 94,23
8  (via drill 0.6 pad 1.5)  (5 unrouted)
  Top 0.406: JP3.8 93,39.3 v90,38 v88,38 | 87.46,7.54 JP4.8
  Top 0.5: R17.2 62,46 61.95,45.95 D3.1 62.35,45.35 v63,46
  Top 1: JP3.8 JP5.8
  Bottom 0.406: 88,5 v88,7 | v88,38 88,36
12V+  (via drill 0.6 pad 1.5)
  Top 0.5: JP6.1 43.34,34.27 C8.+ | R23.2 v59,28 59,28.5 58.5,28.5 57.75,29.25 57.75,31.14 FET2.3 | R5.2 59.15,60.85 v59,61 57.75,62.25 57.75,64.14 U$2.3 | IC1.3 42.41,40 v43,40
  Bottom 0.5: 59,34 v59,28 | 59,34 v59,61 | 43,34.27 v43,40 | C8.+ arc90 45,34.52 45,35 46,35 arc90 47,34 59,34
  pour Bottom (isolate 2, rank 2): 41,43 43,43 44,42 48,35 58,35 60,34 59,33 38,33 37,34
+48-200V  (via drill 0.6 pad 1.5)  (1 unrouted)
  Top 0.406: JP4.2 JP4.1 102.73,13.27 v103,13 | JP3.1 JP5.1 98.14,75 v103,75 | PLUS.1 93,83.28 R43.2
  Top 1: JP3.1 95,80 PLUS.1 | PLUS.1 89.92,82 D7.A | D6.A 89.87,78.87 PLUS.1
  Bottom 0.406: v103,13 103,15 | v103,75 103,72
B-
  pour Top (isolate 1.5, rank 3): 28,118 32,118 33,117 33,35 32,34 26,34 25,35 25,116 27,118
  pour Bottom (isolate 1.5, rank 3): 27,118 32,118 33,117 33,35 32,34 26,34 27,35
BATT-  (via drill 0.6)
  Top 0.5: 8.85,98.15 8,99 8,103.2 D12.A | 17,82.12 R40.1
  Top 1: v9,92 8,93 8,95.55 C9.- 8.85,98.15 | R39.1 17.79,83.67 R40.1 | v18,83 17,82.12 | R49.2 v23,44 D24.A
  Bottom 1: v23,44 23,81 20,83 v18,83 16,85 14,85 9,90 v9,92
BLACK  (via drill 0.6 pad 1.5)  (4 unrouted)
  Top 0.406: 85,59.5 R21.1 | JP4.6 90,9 91,8 | Q8.D 106,133 99,140 85,140 Q2.S
  Top 1: v91.5,49.5 92.29,49.46 v93,49.46 JP3.6 JP5.6 | v91.5,57 91,57 90,58 88,58 | C6.- 82.23,59.77 83.25,59.5 85,59.5 85.5,59.5 87,58 88,58 | C3.2 88.25,58.25 88,58
  Top 1.016: D9.A 81.68,61.05 C6.-
  Bottom 0.406: 91,5 v91,7 | 91.5,51 91,50.5 91,48
  Bottom 1: v91.5,57 91.5,51 v91.5,49.5
COIL1  (via drill 0.6)
  Top 1.5: D22.C D21.C D13.C 22,92.7 22,84 22.3,84.3 D14.C
  other vias: 22,107
  pour Top (isolate 1.5, rank 2): 0,73 0,13 11,13 11,35 25,48 25,116 20,116 20,81 11,73
  pour Bottom (isolate 1.5): 20,116 25,116 25,84 24,83 21,83 20,84 20,93 20,94 20,113
  pour Bottom (isolate 1.5): 0,69 8,69 8,61 0,61
  pour Bottom (isolate 1.5, rank 3): 2,52 10,52 10,13 3,13 2,14 2,17
G1P2
  Top 0.5: IC2.6 52.18,57.27 R32.1
G2P1
  Top 0.5: IC2.5 52.26,59.81 R31.1
GP0  (via drill 0.6 pad 1.5)  (1 unrouted)
  Top 0.406: v53,112 53,112.92 OK3.3
  Top 0.5: IC2.7 51.27,54.73 v53,53 55.15,53 R35.2
GP1R
  Top 0.5: R10.2 55.1,74.1 57,76 | 57,76 59,78 D1.3 | R12.1 56.1,76.9 57,76 | 57,76 57.9,75.1 R8.1 57.93,75.17 R20.2
GP2R
  Top 0.5: R7.2 R11.1 57.25,40.35 57.25,41.25 58.1,42.1 R16.1 58.25,43.15 D3.3 62.29,43.15 R4.2
GP3  (2 unrouted)
  Top 0.5: IC2.4 42,64 | 42,64 42.19,67 | 42.19,67 42.19,67.54 JP2.2 42.46,67.27 JP1.1 | 42,64 R3.1 | LED3.A 41.94,67.25 42.19,67
GP4  (via drill 0.6 pad 1.5)
  Top 0.5: IC2.3 41.92,57 v39.5,57 | R42.2 R44.1 v39,89 R45.S
  Bottom 0.5: v39.5,57 39,57.5 v39,89
GP5
  Top 0.5: JP9.1 36,54.9 R48.1
HIV  (via drill 0.6)
  Top 0.5: D20.A 15.3,31.7 | 15.3,31.7 15,32 | 15.3,31.7 15.3,33.3 v16,34 | PL+.1 6.05,118.05 D11.A 13.68,118.05 JP8.2
  Top 1.5: D15.A D19.A D20.A | Q3.D v5,55
  Bottom 0.5: 16.23,55 R47.1 16,52.58 v16,34 | v16,34 16,32 | 4,85 PL+.1 | v16,34 16,35 17,36
  Bottom 1.5: v5,55 7,55
  pour Bottom (isolate 1.5, rank 2): 0,119 0,82 4,82 4,76 0,76 0,73 9,73 9,60 3,60 3,54 14,54 14,38 20,38 20,74 7,87 7,119
  pour Top (isolate 1.5): 13,37 20,43 17,36 17,5 16,4 13,4
  pour Bottom (isolate 1.5): 13,37 20,43 17,36 17,5 16,4 13,4
  pour Top (isolate 1.5, rank 4): 2,116 2,85 3,84 3,78 1,76 1,74 12,74 12,83 7,88 7,116
MASS  (via drill 0.6 pad 1.5)  (6 unrouted)
  Top 0.406: 90,28 MASS5.1 85,28 84.92,22.92 JP4.9 JP4.10 | D5.A 81.05,5.05 73,3 v31,3 | Q7.S 21.46,-14.46 22,-15 99,-15 Q8.S
  Top 0.5: D5.A 89.13,26.87
  Top 1: MASS5.1 89.13,26.87 90.73,26.87 JP3.10 JP5.10
  Bottom 0.406: v31,3 37,6 35,8
MINUS  (7 unrouted)
  Top 0.5: MAS/B-.1 25.55,37 R49.1 | D14.A D13.A | JP8.1 17.27,117.27 19,119 27,119 30,116 30,112.3 D22.A
  Top 2: D22.A D21.A D13.A | 29,51 29,59.3 D18.A
N$1
  Top 0.5: Q4.G 1.45,77.63
  Top 1: R40.2 1.23,78.79 Q4.G 2.65,78.65 R41.2
N$2  (via drill 0.6 pad 1.5)  (1 unrouted)
  Top 0.5: R32.2 56.55,56 v56,55 | v56,27.75 56.37,27.64 FET2.2
N$3
  Top 1: R15.1 89.1,62.8 R14.2 89.1,62.45 C3.1
N$4
  Top 0.5: U$2.4 59.26,63.9 R6.2 61.35,63.8 R5.1
N$5
  Top 0.5: FET2.6 FET2.5 59.1,36.94 R11.2
N$6
  Top 0.5: R31.2 56.25,60.7 56.25,62.75 56.37,62.87 U$2.2
N$7
  Top 0.5: Q6.2 80.15,69.95 80.25,69.85
  Top 1: 80.25,69.85 80.25,68.5 80.27,67.73 OK1.4 82.77,64.69 C6.+
N$8
  Top 1: R19.1 88.1,46.2 R18.2 88,47.1 88,49 87,50 C5.1
N$9
  Top 0.5: FET2.8 FET2.7 56,36.38 56,35 57,34 60.5,34 61,33.5 R24.1
N$11
  Top 0.5: R6.1 61,66.35 61,67 56.5,67 56.37,67.14 U$2.7 U$2.8
N$12
  Top 0.5: R12.2 53.9,78.8 R13.1 52.35,79.9 51.75,80.5 51.75,81.65 C2.1
N$13
  Top 0.406: R4.1 74.17,41.75 OK2.1
N$14
  Top 0.406: Q5.2 77.73,50.17 C7.+ 78,48.73
  Top 1: OK2.4 81.02,41.73 80,43 78,43 78,48.73
N$15
  Top 0.5: LED3.C 39.73,70.27 JP2.1 41.5,70.77 R2.1
N$16
  Top 0.5: C4.1 55,43 | 55,43 R16.2 | R17.1 55,45.9 55,43
N$17
  Top 0.406: R20.1 75.05,66.59 OK1.1
N$20  (via drill 0.6 pad 1.5)  (1 unrouted)
  Top 0.406: R29.1 76.25,56.75 75,58 | 75,58 73.55,58 R25.1 | 75,58 v76,59 | v76,84 82.68,84 83.18,83.5
  Top 0.5: 82.13,83.87 82,84
  Top 1: 82.13,83.87 83.18,83.5 D7.K
  Bottom 0.406: v76,59 76,61 | 76,82.25 v76,84
N$21
  Top 0.5: U$2.5 U$2.6 57.74,69.74 58,70 R8.2
N$22
  Top 0.5: FET2.4 59.26,30.9 R24.2 63.6,30.9 64,30.5 64,28.1 R23.1
N$23
  Top 0.406: 80,81 75,81 74,80 74,79.05 R26.1
  Top 1: 80,81 80.45,80.55 R22.1 81.55,80 82,80 83.13,78.87 D6.K
N$24
  Top 0.5: 78.05,75.7 78.05,74.55 Q6.3
  Top 1: 78.05,75.7 R28.2
N$25
  Top 1.016: JP3.2 JP5.2
N$26
  Top 0.5: 79.8,77.45 78.75,78.5 | 78.75,78.75 78.5,79
  Top 1: R22.2 79.8,77.45 | 78.75,78.5 78.75,78.75 | 78.5,79 77.95,79 R28.1
N$27
  Top 0.406: 77.7,70.3 74,74 74,74.95 R26.2
  Top 0.5: D9.C 77.85,67.95 Q6.1 77.7,70.3
N$28
  Top 1: R29.2 79.7,56.75 R30.1
N$31
  Top 0.406: D8.C 71.75,53.2 R25.2 74.05,54.95 75,54 76.2,54 Q5.1
N$33
  Top 0.5: Q5.3 81.3,52.75 R30.2
N$34
  Top 1: JP3.9 JP5.9
N$35
  Top 0.406: OK3.1 61.73,116.27 64,114 64.35,114 R33.1 67.12,114.4 R34.S 69.35,114.25 R9.2
N$36
  Top 0.406: R33.2 67.08,116.6 R34.A 72.91,116.79 D10.C 78.16,116.7 R1.1
N$37
  Top 0.406: OK3.2 60.27,113.73 62,112 66.98,112 R34.E 69.31,111.71 R9.1 71.6,111.9 D10.A 82.7,113.3 84,112 85.61,112 B1.-
N$38
  Top 0.406: B1.~2 97.7,115.3 AC1.1
N$39
  Top 0.406: B1.~1 93.69,102.31 AC2.1
N$40
  Top 0.406: B1.+ 86.31,115.69 85,117 R1.2
N$41
  Top 0.5: 43.6,92.1 D23.C | 43.6,92.1 R44.2 37.29,92.1 R45.A | 43.6,92.1 43.6,92.12 R43.1
N$42
  Top 1: OK4.2 JP7.1
N$43
  Top 0.5: 14,85 15,85 | R46.2 13,80.5
  Top 1: OK4.3 17.27,87.27 15,85 | 14,85 13,84 13,80.5 | R41.1 13.75,79.75 R46.2
N$44
  Top 1: OK4.1 JP7.2
N$45
  Top 1: R39.2 1.81,57.54 Q3.G 0.71,58.37 R46.1
N$46
  Top 0.5: R48.2 41,54 42,55 42,54.92 IC2.2
N$48
  Top 0.5: OK4.4 14.73,89.27 | 11,94.25 C9.+ | Q10.2 17,103.15 17,102 13,102 12,101
  Top 1: 14.73,89.27 11,93 11,94.25 | C9.+ 10.65,94.9 11.5,95.75 11.5,100.5 12,101
N$49
  Top 0.5: R36.1 8.95,110.5 R37.1 9,111.45 9,113 9.95,113.95 D11.K
N$50
  Top 0.5: R37.2 13,111 15,113 15.8,113 R38.1
N$51
  Top 0.5: Q10.1 12.25,104.3 D12.C 12.05,104.1 R36.2
N$52  (2 unrouted)
NEGATIV
  Top 0.5: R45.E 37,86.19 37,85 | U$2.1 54.84,64 53,64 | FET2.1 54.84,31 53,31 | 40,43 IC1.2 40,38
  pour Top (isolate 1.5, rank 4): 35,85 77,85 77,25 35,25
  pour Bottom (isolate 1.5, rank 3): 36,85 77,85 77,25 36,25
PUMP+  (3 unrouted)
  Top 0.5: Q1.D 22,144 54,144 | 54,144 80,144 82,142 Q2.D | 54,144 COIL2.1
Q1
  Top 0.5: Q10.3 R38.2
RED  (via drill 0.6 pad 1.5)  (3 unrouted)
  Top 0.406: v74,49 71.8,49 D8.A | JP4.5 90,15 93,19 v97,19 | JP5.5 98.46,55
  Top 0.5: v97,55.5 95.71,55.5 JP3.5 | Q1.S 24.54,133.46 25,133 -2,133 -9,126 -9,2 -2,-5 22,-5 24,-7 Q7.D
  Top 1: 82.1,49 C7.- | 82.1,49 R27.2 | 84,50 83.1,50 82.1,49 | 84,50 C5.2 | 84,50 84,51 86,53 93,53 94.54,54.54 JP3.5 JP5.5 | v82.75,49.75 84,50
  Bottom 0.406: v97,55.5 97,53.5 | v97,19 97,21.25
  Bottom 1: v74,49 74.5,52 82,52 v82.75,49.75
SNUB
  pour Top (isolate 1.5, rank 2): 22,32 27,32 28,31 28,5 25,2 20,2 21,3 21,31
  pour Bottom (isolate 1.5, rank 2): 22,32 27,32 28,31 28,5 25,2 20,2 21,3 21,31
VDD  (via drill 0.6 pad 1.5)  (2 unrouted)
  Top 0.406: v49,118 49,117.08 OK3.4
  Top 0.5: JP1.2 46,64.98 | JP1.2 46,53.25 44,53 43,52 42.38,52 IC2.1 | C17.1 42.61,51.77 IC2.1 | IC2.1 41,51 39,51 38.13,50.13 C1.+ 38,47.19 38,43 38.09,41.91 IC1.1 | JP1.2 48.73,64.73 v49,65
X
  Top 1: OK2.3 83,44.27 | 83,44.27 84,44.27 | 84,44.27 84.58,44.27 D4.1 | R18.1 85.9,46.17 84,44.27 | 83,44.27 R27.1
XX
  Top 1: OK1.3 83.27,69.27 83.5,69.5 | 83.5,69.5 84,70 84,73 85,74 86.85,74 D2.1 | 83.5,69.5 84,69 R15.2 87,65.15 R21.2

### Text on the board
Top: MICHAEL5.net | 1 | BLK | 10 | BLK
Bottom: 1 | BLK | 10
